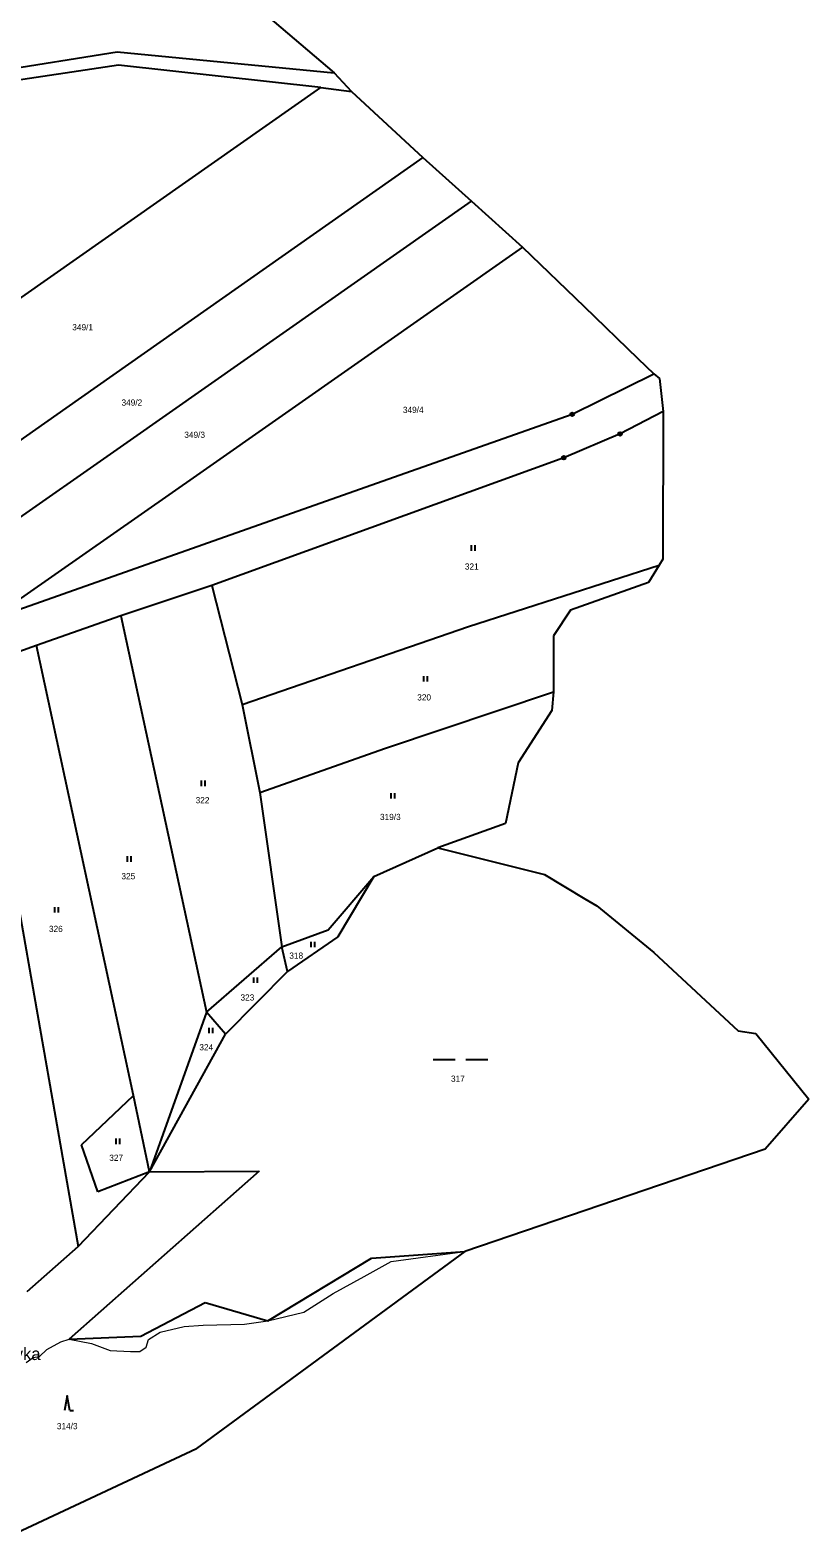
# Model space of a CAD drawing. Extents: x -820420 to -815896, y -1105820 to -1103643.
# Drawn here: x -816109.6 to -815895.6, y -1104527.4 to -1104113 of the extents above; entities that cross this region are included whole.
import ezdxf
from ezdxf.enums import TextEntityAlignment as Align

# ---------------------------------------------------------------- set-up
doc = ezdxf.new("R2010")
doc.units = 0
doc.header["$LTSCALE"] = 0.68
for name, color, linetype, lineweight in [('1', 7, 'Continuous', 25), ('3', 7, 'Continuous', 25), ('4', 7, 'Continuous', 13), ('7', 7, 'Continuous', 13), ('8', 7, 'Continuous', 25)]:
    doc.layers.add(name, color=color, linetype=linetype, lineweight=lineweight)
doc.layers.add('2', color=7, linetype='Continuous')

msp = doc.modelspace()

# ---------------------------------------------------------------- linework, layer by layer
at = {"layer": '1'}
for p, q in [((-816044.37, -1104109.2), (-816026.06, -1104124.71)), ((-816125.76, -1104125.41), (-816085.67, -1104118.99)), ((-816085.33, -1104122.62), (-816121.08, -1104127.95)), ((-816085.67, -1104118.99), (-816026.06, -1104124.71)), ((-816029.73, -1104128.78), (-816085.33, -1104122.62)), ((-816026.06, -1104124.71), (-816021.28, -1104129.87)), ((-816129.94, -1104199), (-816029.73, -1104128.78)), ((-816029.73, -1104128.78), (-816021.28, -1104129.87)), ((-816021.28, -1104129.87), (-816001.62, -1104148.05)), ((-816001.62, -1104148.05), (-816099.78, -1104216.88)), ((-816001.62, -1104148.05), (-815988.3, -1104159.97)), ((-816081.97, -1104225.7), (-815988.3, -1104159.97)), ((-815988.3, -1104159.97), (-815974.31, -1104172.7)), ((-815974.31, -1104172.7), (-816062.92, -1104234.79)), ((-815974.31, -1104172.7), (-815957.36, -1104188.99)), ((-815957.36, -1104188.99), (-815942.55, -1104203.23)), ((-815942.55, -1104203.23), (-815938.15, -1104207.46)), ((-815960.61, -1104218.6), (-815938.15, -1104207.46)), ((-815938.15, -1104207.46), (-815936.62, -1104208.8)), ((-815936.62, -1104208.8), (-815935.58, -1104217.83)), ((-816099.78, -1104216.88), (-816175.75, -1104270.17)), ((-815935.58, -1104217.83), (-815947.43, -1104223.98)), ((-815935.58, -1104217.83), (-815935.73, -1104258.4)), ((-816025.3, -1104241.35), (-815960.61, -1104218.6)), ((-816163.29, -1104282.54), (-816081.97, -1104225.7)), ((-815947.43, -1104223.98), (-815962.94, -1104230.55)), ((-815962.94, -1104230.55), (-816059.67, -1104265.69)), ((-816062.92, -1104234.79), (-816120.6, -1104275)), ((-816120.6, -1104275), (-816025.3, -1104241.35)), ((-815935.73, -1104258.4), (-815936.71, -1104260.03)), ((-815989.14, -1104276.94), (-815936.71, -1104260.03)), ((-815936.71, -1104260.03), (-815939.61, -1104264.84)), ((-816059.67, -1104265.69), (-816084.66, -1104274)), ((-816059.67, -1104265.69), (-816051.3, -1104298.37)), ((-815939.61, -1104264.84), (-815961.07, -1104272.4)), ((-816084.66, -1104274), (-816107.82, -1104282.15)), ((-816084.66, -1104274), (-816061.09, -1104382.96)), ((-815961.07, -1104272.4), (-815965.72, -1104279.54)), ((-816051.3, -1104298.37), (-815989.14, -1104276.94)), ((-815965.72, -1104279.54), (-815965.74, -1104294.92)), ((-816107.82, -1104282.15), (-816125.8, -1104288.47)), ((-816081.15, -1104405.86), (-816107.82, -1104282.15)), ((-816011.9, -1104310.34), (-815965.74, -1104294.92)), ((-815965.74, -1104294.92), (-815966.25, -1104300.02)), ((-816051.3, -1104298.37), (-816046.5, -1104322.6)), ((-815966.25, -1104300.02), (-815975.42, -1104314.43)), ((-816046.5, -1104322.6), (-816011.9, -1104310.34)), ((-815975.42, -1104314.43), (-815978.95, -1104331.09)), ((-816046.5, -1104322.6), (-816040.38, -1104365.02)), ((-815978.95, -1104331.09), (-815997.54, -1104337.77)), ((-816015.17, -1104345.69), (-815997.54, -1104337.77)), ((-815997.54, -1104337.77), (-815968.22, -1104345.09)), ((-816027.65, -1104360.32), (-816015.17, -1104345.69)), ((-816015.17, -1104345.69), (-816024.99, -1104362.27)), ((-815968.22, -1104345.09), (-815957.15, -1104351.76)), ((-816113.17, -1104351.67), (-816096.37, -1104447.33)), ((-815957.15, -1104351.76), (-815953.87, -1104353.74)), ((-815953.87, -1104353.74), (-815938.17, -1104366.51)), ((-816040.38, -1104365.02), (-816027.65, -1104360.32)), ((-816024.99, -1104362.27), (-816038.87, -1104371.77)), ((-816061.09, -1104382.96), (-816040.38, -1104365.02)), ((-816038.87, -1104371.77), (-816040.38, -1104365.02)), ((-815938.17, -1104366.51), (-815914.97, -1104388.04)), ((-816038.87, -1104371.77), (-816055.9, -1104388.98)), ((-816061.09, -1104382.96), (-816076.74, -1104426.8)), ((-816055.9, -1104388.98), (-816061.09, -1104382.96)), ((-815914.97, -1104388.04), (-815910.13, -1104388.84)), ((-816076.74, -1104426.8), (-816055.9, -1104388.98)), ((-815910.13, -1104388.84), (-815895.57, -1104406.84)), ((-816095.43, -1104419.42), (-816081.15, -1104405.86)), ((-816076.74, -1104426.8), (-816081.15, -1104405.86)), ((-815895.57, -1104406.84), (-815907.55, -1104420.64)), ((-816090.95, -1104432.38), (-816095.43, -1104419.42)), ((-815907.55, -1104420.64), (-815990.12, -1104448.78)), ((-816046.68, -1104426.7), (-816098.85, -1104472.87)), ((-816096.37, -1104447.33), (-816076.74, -1104426.8)), ((-816076.74, -1104426.8), (-816090.95, -1104432.38)), ((-816076.74, -1104426.8), (-816046.68, -1104426.7)), ((-816110.45, -1104459.72), (-816096.37, -1104447.33)), ((-815990.12, -1104448.78), (-816063.83, -1104502.87)), ((-816015.78, -1104450.61), (-815990.12, -1104448.78)), ((-816044.23, -1104467.76), (-816015.78, -1104450.61)), ((-816079.2, -1104471.99), (-816061.49, -1104462.75)), ((-816061.49, -1104462.75), (-816044.23, -1104467.76)), ((-816098.85, -1104472.87), (-816079.2, -1104471.99)), ((-816116.27, -1104527.45), (-816063.83, -1104502.87))]:
    msp.add_line(p, q, dxfattribs=at)
at = {"layer": '3'}
for p, q in [((-815988.241, -1104256.11), (-815988.241, -1104254.61)), ((-815987.24, -1104256.11), (-815987.24, -1104254.61)), ((-816001.341, -1104292.08), (-816001.341, -1104290.58)), ((-816000.34, -1104292.08), (-816000.34, -1104290.58)), ((-816062.511, -1104320.8), (-816062.511, -1104319.3)), ((-816061.51, -1104320.8), (-816061.51, -1104319.3)), ((-816010.391, -1104324.24), (-816010.391, -1104322.74)), ((-816009.39, -1104324.24), (-816009.39, -1104322.74)), ((-816082.861, -1104341.59), (-816082.861, -1104340.09)), ((-816081.86, -1104341.59), (-816081.86, -1104340.09)), ((-816102.771, -1104355.56), (-816102.771, -1104354.06)), ((-816101.77, -1104355.56), (-816101.77, -1104354.06)), ((-816032.311, -1104365.09), (-816032.311, -1104363.59)), ((-816031.31, -1104365.09), (-816031.31, -1104363.59)), ((-816048.131, -1104374.91), (-816048.131, -1104373.41)), ((-816047.13, -1104374.91), (-816047.13, -1104373.41)), ((-816060.391, -1104388.73), (-816060.391, -1104387.23)), ((-816059.39, -1104388.73), (-816059.39, -1104387.23)), ((-815998.799, -1104395.93), (-815992.799, -1104395.93)), ((-815989.799, -1104395.93), (-815983.799, -1104395.93)), ((-816085.981, -1104419.22), (-816085.981, -1104417.72)), ((-816084.98, -1104419.22), (-816084.98, -1104417.72)), ((-816098.65, -1104492.4), (-816097.654, -1104492.4))]:
    msp.add_line(p, q, dxfattribs=at)
msp.add_lwpolyline([(-816098.65, -1104492.4), (-816099.4, -1104488.4), (-816100.15, -1104492.4)], dxfattribs=at)
at = {"layer": '4'}
for p, q in [((-816010.34, -1104451.47), (-815990.12, -1104448.78)), ((-816017.79, -1104455.63), (-816010.34, -1104451.47)), ((-816026.3, -1104460.29), (-816017.79, -1104455.63)), ((-816034.4, -1104465.45), (-816026.3, -1104460.29)), ((-816044.23, -1104467.76), (-816034.4, -1104465.45)), ((-816077.09, -1104472.97), (-816073.86, -1104470.89)), ((-816073.86, -1104470.89), (-816067.27, -1104469.38)), ((-816067.27, -1104469.38), (-816062.04, -1104469.02)), ((-816062.04, -1104469.02), (-816050.67, -1104468.68)), ((-816050.67, -1104468.68), (-816044.23, -1104467.76)), ((-816105, -1104475.68), (-816101.13, -1104473.6)), ((-816101.13, -1104473.6), (-816098.85, -1104472.87)), ((-816098.85, -1104472.87), (-816092.71, -1104474.04)), ((-816092.71, -1104474.04), (-816087.62, -1104475.91)), ((-816079.45, -1104476.26), (-816077.73, -1104475.05)), ((-816077.73, -1104475.05), (-816077.09, -1104472.97)), ((-816110.66, -1104479.26), (-816108.72, -1104477.9)), ((-816108.72, -1104477.9), (-816107, -1104477.62)), ((-816107, -1104477.62), (-816105, -1104475.68)), ((-816087.62, -1104475.91), (-816082.03, -1104476.19)), ((-816082.03, -1104476.19), (-816079.45, -1104476.26))]:
    msp.add_line(p, q, dxfattribs=at)
at = {"layer": '8'}
for centre, radius in [((-815960.61, -1104218.5999), 0.5), ((-815960.61, -1104218.5999), 0.0303), ((-815947.43, -1104223.9799), 0.5), ((-815947.43, -1104223.9799), 0.0303), ((-815962.94, -1104230.5499), 0.5), ((-815962.94, -1104230.5499), 0.0303)]:
    msp.add_circle(centre, radius, dxfattribs=at)

# ---------------------------------------------------------------- texts
at = {"layer": '2'}
for s, p in [('349/1', (-816095.16, -1104195.525)), ('349/2', (-816081.63, -1104216.225)), ('349/4', (-816004.3, -1104218.235)), ('349/3', (-816064.37, -1104225.075)), ('321', (-815988.209, -1104261.295)), ('320', (-816001.309, -1104297.265)), ('322', (-816062.209, -1104325.515)), ('319/3', (-816010.59, -1104330.135)), ('325', (-816082.609, -1104346.415)), ('326', (-816102.519, -1104360.905)), ('318', (-816036.459, -1104368.255)), ('323', (-816049.879, -1104379.745)), ('324', (-816061.189, -1104393.445)), ('317', (-815992.019, -1104402.075)), ('327', (-816085.949, -1104423.815)), ('314/3', (-816099.4, -1104497.595))]:
    msp.add_text(s, height=1.7, dxfattribs=at).set_placement(p, align=Align.CENTER)
at = {"layer": '7'}
msp.add_text('Mihovka', height=3.4, dxfattribs=at).set_placement((-816115.199, -1104478.57), align=Align.CENTER)

doc.saveas('drawing.dxf')
